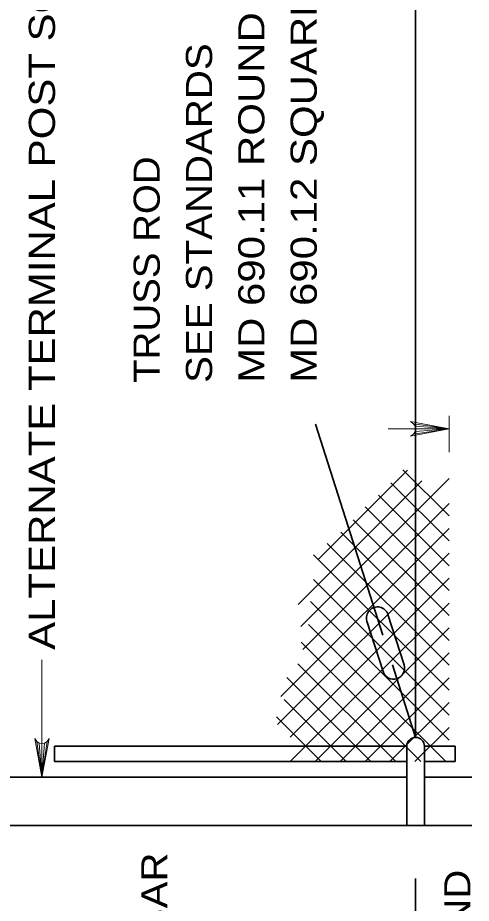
# Model space of a CAD drawing. Extents: x -46.1 to -39.3, y 101.7 to 111.8.
# Drawn here: x -44.121 to -43.081, y 105.103 to 107.135 of the extents above; entities that cross this region are included whole.
import ezdxf

# ---------------------------------------------------------------- set-up
doc = ezdxf.new("R2010")
doc.units = 0
doc.header["$LTSCALE"] = 0.024
for name, color, linetype, lineweight in [('1', 7, 'Continuous', 35), ('10', 7, 'Continuous', 13), ('12', 7, 'Continuous', 53), ('6', 7, 'Continuous', 13)]:
    doc.layers.add(name, color=color, linetype=linetype, lineweight=lineweight)

msp = doc.modelspace()

# ---------------------------------------------------------------- linework, layer by layer
at = {"layer": '1'}
for p, q in [((-43.20892, 111.18012), (-43.20892, 105.48315)), ((-43.28369, 105.71769), (-43.43812, 106.20223)), ((-43.23548, 105.6496), (-43.27229, 105.7651)), ((-43.2836, 105.63427), (-43.3204, 105.74975)), ((-43.20892, 105.48315), (-43.26212, 105.65004)), ((-44.03721, 105.42758), (-44.03721, 105.46294)), ((-43.22912, 105.46294), (-44.03721, 105.46294)), ((-43.22912, 105.28113), (-43.22912, 105.46294)), ((-43.18873, 105.28113), (-43.18873, 105.46294)), ((-43.11802, 105.46294), (-43.18873, 105.46294)), ((-43.11802, 105.42758), (-43.11802, 105.46294)), ((-43.22912, 105.42758), (-44.03721, 105.42758)), ((-43.11802, 105.42758), (-43.18873, 105.42758)), ((-44.93873, 105.39223), (-43.22912, 105.39223)), ((-43.18873, 105.39223), (-43.08015, 105.39223)), ((-45.05994, 105.28113), (-43.08015, 105.28113)), ((-43.20892, 104.33669), (-43.20892, 105.15927))]:
    msp.add_line(p, q, dxfattribs=at)
for centre, radius, start, end in [((-43.29635, 105.75743), 0.02525, 17.67761, 197.67848), ((-43.25954, 105.64194), 0.02525, 197.67941, 17.67668), ((-43.20893, 105.46294), 0.0202, 0, 180)]:
    msp.add_arc(centre, radius, start, end, dxfattribs=at)
at = {"layer": '10'}
for p, q in [((-43.13229, 106.13781), (-43.13229, 106.22154)), ((-43.27177, 106.19125), (-43.13229, 106.19125)), ((-44.06585, 105.39223), (-44.06585, 105.66142))]:
    msp.add_line(p, q, dxfattribs=at)
for points in [[(-43.13229, 106.19125), (-43.22056, 106.17469), (-43.21377, 106.17942), (-43.21025, 106.18533), (-43.20925, 106.19125), (-43.21025, 106.19717), (-43.21377, 106.20308), (-43.22056, 106.20779), (-43.13229, 106.19125), (-43.21377, 106.20308), (-43.21025, 106.19717), (-43.13229, 106.19125), (-43.20925, 106.19125), (-43.21025, 106.18533), (-43.13229, 106.19125), (-43.21377, 106.17942)], [(-44.06585, 105.39223), (-44.0824, 105.4805), (-44.07769, 105.47371), (-44.07177, 105.47019), (-44.06585, 105.46919), (-44.05994, 105.47019), (-44.054, 105.47371), (-44.04929, 105.4805), (-44.06585, 105.39223), (-44.054, 105.47371), (-44.05994, 105.47019), (-44.06585, 105.39223), (-44.06585, 105.46919), (-44.07177, 105.47019), (-44.06585, 105.39223), (-44.07769, 105.47371)]]:
    msp.add_lwpolyline(points, dxfattribs=at)
at = {"layer": '6'}
for p, q in [((-43.43229, 105.8915), (-43.22752, 106.09625)), ((-43.13229, 105.99148), (-43.23792, 106.0971)), ((-43.47852, 105.7881), (-43.19458, 106.07206)), ((-43.4719, 105.7376), (-43.13229, 106.07719)), ((-43.13229, 105.93435), (-43.26537, 106.06742)), ((-43.13229, 105.87721), (-43.29394, 106.03885)), ((-43.46765, 105.68473), (-43.13229, 106.02006)), ((-43.13229, 105.82006), (-43.32469, 106.01246)), ((-43.13229, 105.76294), (-43.35215, 105.98279)), ((-43.518, 105.57723), (-43.13229, 105.96292)), ((-43.13229, 105.70579), (-43.38071, 105.95421)), ((-43.13229, 105.64865), (-43.41148, 105.92781)), ((-43.52542, 105.51265), (-43.13229, 105.90577)), ((-43.13229, 105.5915), (-43.44333, 105.90254)), ((-43.49685, 105.48408), (-43.13229, 105.84865)), ((-43.13229, 105.53437), (-43.44337, 105.84546)), ((-43.49621, 105.42758), (-43.13229, 105.7915)), ((-43.13229, 105.47723), (-43.45002, 105.79494)), ((-43.13979, 105.42758), (-43.45446, 105.74225)), ((-43.43906, 105.42758), (-43.13229, 105.73435)), ((-43.19694, 105.42758), (-43.47096, 105.7016)), ((-43.38194, 105.42758), (-43.13229, 105.67721)), ((-43.25408, 105.42758), (-43.47869, 105.65221)), ((-43.31123, 105.42758), (-43.50396, 105.62033)), ((-43.32479, 105.42758), (-43.13229, 105.62008)), ((-43.36835, 105.42758), (-43.5106, 105.56983)), ((-43.26765, 105.42758), (-43.13229, 105.56294)), ((-43.4255, 105.42758), (-43.52821, 105.53029)), ((-43.2105, 105.42758), (-43.13229, 105.50579))]:
    msp.add_line(p, q, dxfattribs=at)

# ---------------------------------------------------------------- texts
at = {"layer": '12'}
for s, width, p in [('MD 690.12 SQUARE CONSTRUCTION', 1.2, (-43.43555, 106.29677)), ('MD 690.11 ROUND CONSTRUCTION', 1.2, (-43.55555, 106.29677)), ('ALTERNATE TERMINAL POST SQUARE', 1.2, (-44.03584, 105.68412)), ('SEE STANDARDS', 1.15, (-43.67555, 106.29677)), ('TRUSS ROD', 1.1, (-43.79555, 106.29677)), ('STRETCHER BAR', 1.15, (-43.77788, 104.43984)), ('TENSION BAND', 1.15, (-43.08325, 104.48745))]:
    msp.add_text(s, height=0.06, rotation=90, dxfattribs=dict(at, width=width)).set_placement(p)

doc.saveas('drawing.dxf')
